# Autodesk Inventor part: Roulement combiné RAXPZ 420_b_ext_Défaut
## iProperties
Shininess: 64.0
Length Units: 11269
Angle Units: 11279
Time Units: 11290
Mass Units: 11283
Length Display Precision: 3
Angle Display Precision: 2
Compacted: True
Part Number: Roulement combiné RAXPZ 420_b_ext_Défaut
Document SubType Name: Modeling
Created: 2006-01
Material: Par défaut
Designer: riri
Density: 0.0
Volumn: 0.0
Area: 0.0
PropertySet Name: Model Information
Control State: 0
Master: False
Checked Out: False
Author: riri
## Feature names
1. Base1
